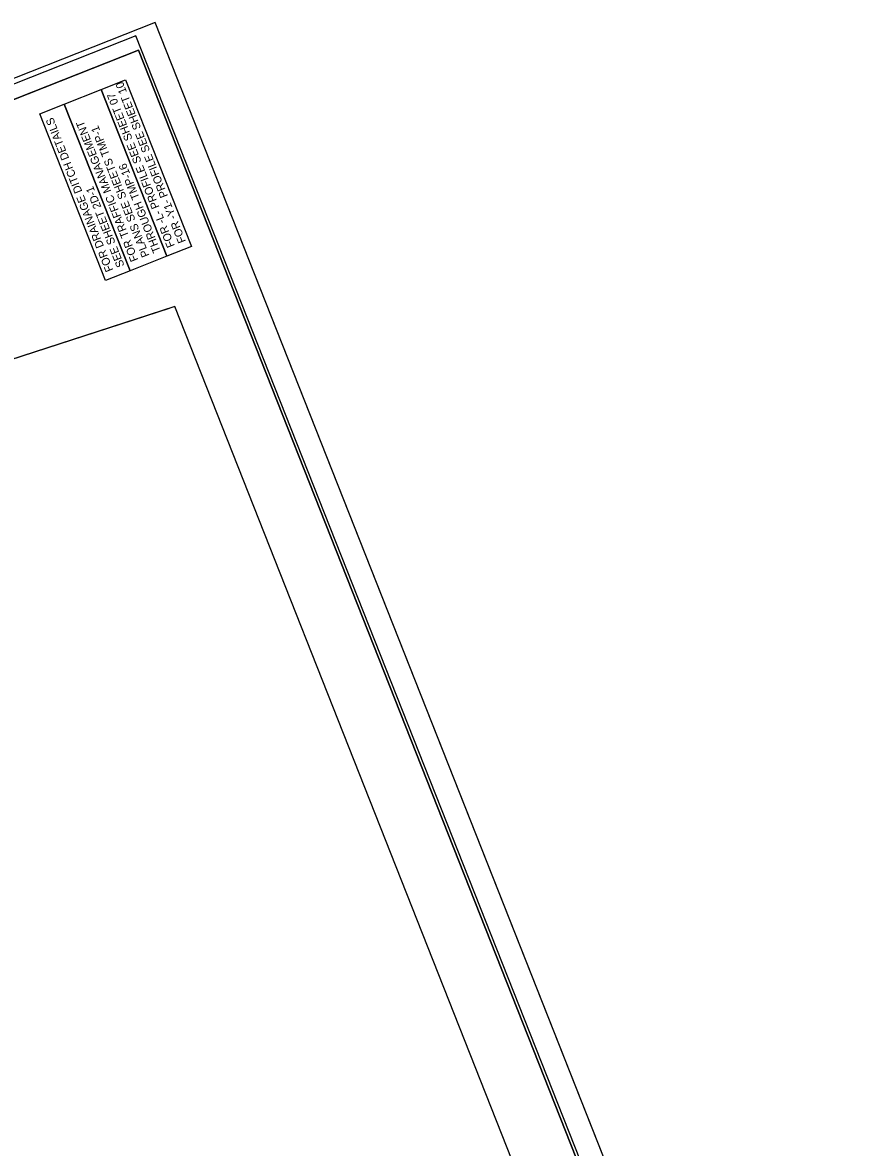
# Model space of a CAD drawing. Extents: x 1250793 to 1252430, y 745882 to 747850.
# Drawn here: x 1251695 to 1252430, y 746866 to 747850 of the extents above; entities that cross this region are included whole.
import ezdxf

# ---------------------------------------------------------------- set-up
doc = ezdxf.new("R2010")
doc.units = 0
for name, color, linetype in [('Matchline', 7, 'Continuous'), ('Prop Grid Mask', 7, 'Continuous'), ('Prop PFL Text', 7, 'Continuous'), ('Sheet Clip Boundary CELL', 7, 'Continuous'), ('Sheet Cutting Line CELL', 7, 'Continuous'), ('Sheet Plan CELL', 7, 'Continuous'), ('Sheet Plan Layout CELL', 7, 'Continuous'), ('Sheet Plot Border Inside CELL', 7, 'Continuous'), ('Sheet Plot Border Outside CELL', 7, 'Continuous')]:
    doc.layers.add(name, color=color, linetype=linetype)

msp = doc.modelspace()

# ---------------------------------------------------------------- linework, layer by layer
at = {"layer": 'Matchline'}
msp.add_line((1251823.24, 747599.85), (1251214.41, 747402.56), dxfattribs=at)
at = {"layer": 'Prop Grid Mask'}
for points in [[(1251821.3, 747645.68), (1251763.65, 747791.49), (1251785.04, 747799.94), (1251842.69, 747654.13)], [(1251788.94, 747632.88), (1251731.28, 747778.69), (1251763.65, 747791.49), (1251821.3, 747645.68)], [(1251767.55, 747624.42), (1251709.9, 747770.23), (1251731.29, 747778.69), (1251788.94, 747632.88)]]:
    msp.add_lwpolyline(points, close=True, dxfattribs=at)
at = {"layer": 'Sheet Clip Boundary CELL'}
msp.add_lwpolyline([(1252280.38, 746457.5), (1252280.38, 746457.5), (1251828.05, 747601.41), (1251828.05, 747601.41), (1251079.3, 747358.78), (1251104.49, 747295.07), (1250907.82, 747217.3), (1251353.02, 746091.38)], close=True, dxfattribs=at)
at = {"layer": 'Sheet Cutting Line CELL'}
msp.add_line((1252430, 746284.43), (1251810.97, 747849.98), dxfattribs=at)
at = {"layer": 'Sheet Plan CELL'}
for points in [[(1250819.83, 747439.83), (1251371.41, 746044.88), (1252347.85, 746430.97), (1251796.28, 747825.9)], [(1252347.85, 746430.97), (1251371.44, 746044.87), (1250893.39, 747253.76), (1251032.94, 747308.96), (1250959.39, 747494.98), (1251796.28, 747825.9)]]:
    msp.add_lwpolyline(points, close=True, dxfattribs=at)
at = {"layer": 'Sheet Plan Layout CELL'}
msp.add_lwpolyline([(1251371.44, 746044.87), (1252347.85, 746430.97), (1251796.29, 747825.89), (1251016.52, 747517.56), (1251104.49, 747295.07), (1250907.82, 747217.3)], close=True, dxfattribs=at)
at = {"layer": 'Sheet Plot Border Inside CELL'}
msp.add_lwpolyline([(1252406.62, 746289.16), (1251794.01, 747838.43), (1250812.93, 747450.51), (1251425.54, 745901.23)], close=True, dxfattribs=at)
at = {"layer": 'Sheet Plot Border Outside CELL'}
msp.add_lwpolyline([(1252430, 746284.43), (1251810.97, 747849.98), (1250792.68, 747447.34), (1251411.72, 745881.79)], close=True, dxfattribs=at)

# ---------------------------------------------------------------- texts
at = {"layer": 'Prop PFL Text'}
for s, rotation, p in [('FOR -Y1- PROFILE SEE SHEET 10', 111.57435, (1251837.99, 747658.56)), ('FOR -L- PROFILE SEE SHEET 07', 111.57435, (1251828.22, 747654.7)), ('FOR DRAINAGE DITCH DETAILS ', 111.57435, (1251774.47, 747633.44)), ('FOR TRAFFIC MANAGEMENT ', 111.57478, (1251796.37, 747642.37)), ('PLANS SEE SHEETS TMP-1 ', 111.57478, (1251806.13, 747646.23)), ('THROUGH TMP-16', 111.57478, (1251815.89, 747650.09)), ('SEE SHEET 2D-1', 111.57435, (1251784.23, 747637.31))]:
    msp.add_text(s, height=7, rotation=rotation, dxfattribs=at).set_placement(p)

doc.saveas('drawing.dxf')
